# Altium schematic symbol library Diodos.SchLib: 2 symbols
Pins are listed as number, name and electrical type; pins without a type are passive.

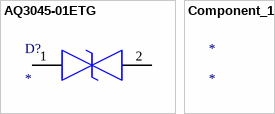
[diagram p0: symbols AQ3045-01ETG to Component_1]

## AQ3045-01ETG
designator D?
TVS Diode (Bi-directional); Manufacturer_Name: LITTELFUSE; Manufacturer_Part_Number: AQ3045-01ETG; Description: LITTELFUSE - AQ3045-01ETG - DIODE
footprint AQ304501ETG
pins: 1, 2

## Component_1
designator *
